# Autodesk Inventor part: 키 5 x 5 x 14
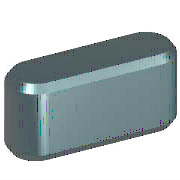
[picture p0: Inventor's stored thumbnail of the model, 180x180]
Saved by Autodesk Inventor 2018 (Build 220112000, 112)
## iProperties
IsCustomPart: 1
Created: 2012-02
Part Number: 키 5 x 5 x 14
Material: 강철, 연강
Description: 키 및 해당 키홈
Document SubType Name: Modeling
Standard: KS B 1311
Designer: mduedu
Standards Organization: KS
Language: ko-KR
Size Designation: 4 x 4 x 12
Categories: <MemberInstance><Categories><Category DisplayName="샤프트 부품" InternalName="7f7aeb1f-a693-4053-b835-cee3144e0d98" Mnemonic="SHFT"><Category DisplayName="키" Interna
Density: 1 g/cm^3
Appearance: 노란색
Author: mduedu
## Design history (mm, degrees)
workplane "Work Plane1"
workplane "Work Plane2"
sketch "스케치1"
  geometry: L1 (2.5, 2.5)-(11.5, 2.5); L2 (11.5, -2.5)-(2.5, -2.5); L3 (0, 8.9)-(0, -4.4) reference; L4 (-2.8, 0)-(16.8, 0) reference; L5 (14, 0)-(14, 7); A1 r 2.5 centre (2.5, 0) between (2.5, 2.5) and (2.5, -2.5); A2 r 2.5 centre (11.5, 0) between (11.5, -2.5) and (11.5, 2.5)
  constraints: 6 end point, 5 point on circle, 4 tangent, 3 point on line, 2 centre point, 1 horizontal, 1 parallel, 1 perpendicular
  dimensions: "d0" = 2.5 radius of A1 (= 0.5 x PB); "d13" = 2.5 radius of A2 (= 0.5 x PB); "d14" = 14 distance between parallel lines of L5 L3 (= NLG)
extrude "본체1" new body sketch "스케치1" taper "d3" = 0 deg; stored distance "d4" = 10
workplane "Work Plane3"
body "Solid1"
chamfer "모따기1" distance "d8" = 0.25 (= PHH); stored, may be unused: second distance "d9" = 0.25 (= PHH), angle "d15" = 45 deg
other parameters: "d1" = -3 (= -PNT), "d2" = 2 (= PH - PNT), "NLG" = 14 [user parameter; used in 3 equation terms], "PB" = 5 [user parameter; used in 2 equation terms], "PNT" = 3 [user parameter; used in 2 equation terms], "PH" = 5 [user parameter; used in 1 equation term], "PHH" = 0.25 [user parameter; used in 2 equation terms], "d10" = 0, "d16" = 0, "d17" = 0, "d18" = 0, "PLB2" = 14 (= NLG) [user parameter], "WDMAX" = 12 [user parameter], "PLB1" = 14 (= NLG) [user parameter], "RR" = 0.08 [user parameter], "PUEB" = 1.8 [user parameter]
